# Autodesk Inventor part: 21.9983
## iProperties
Created: 2009-08
Part Number: 21.9983
Document SubType Name: Modeling
Designer: Administrator
Density: 7.85 g/cm^3
Material: Steel
Description: M8x16 Button Head Flange Screw
Mass: 9.80232 g
Surface Area: 12.8053 cm^2
Volume: 1.2487 cm^3
Author: Administrator
Title: M8x16 Button Head Flange Screw
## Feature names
1. Base1
